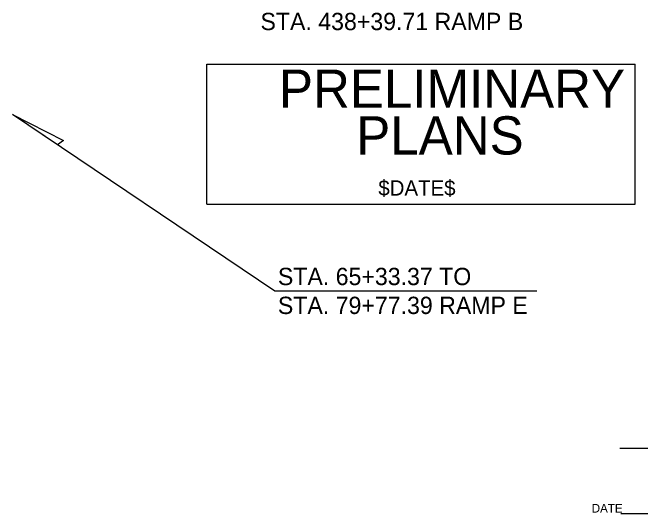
# Model space of a CAD drawing. Extents: x 2121385 to 2181200, y 132498 to 161273.
# Drawn here: x 2167716 to 2176434, y 136610 to 143556 of the extents above; entities that cross this region are included whole.
import ezdxf

# ---------------------------------------------------------------- set-up
doc = ezdxf.new("R2010")
doc.units = 0
for name, color, linetype in [('4', 7, 'Continuous'), ('5', 7, 'Continuous'), ('SHT_Date_Stamp', 7, 'Continuous'), ('SHT_Standard_Sheet_Lines', 7, 'Continuous'), ('SHT_Standard_Sheet_Txt', 7, 'Continuous'), ('TOPO_Concrete', 7, 'Continuous')]:
    doc.layers.add(name, color=color, linetype=linetype)

# ---------------------------------------------------------------- blocks, each defined once
blk = doc.blocks.new('Stamp_Date_Stamp')
at = {"layer": 'SHT_Date_Stamp'}
blk.add_text('$DATE$', height=0.12, dxfattribs=at).set_placement((-2.1838, -1.3809))

msp = doc.modelspace()

# ---------------------------------------------------------------- linework, layer by layer
at = {"layer": '5'}
msp.add_lwpolyline([(2167715.5, 142142.7), (2168423.1, 141780), (2168337.7, 141723.9)], close=True, dxfattribs=at)
msp.add_lwpolyline([(2174994.3, 139690.5), (2171359.3, 139690.5), (2167715.5, 142142.7)], dxfattribs=at)
at = {"layer": 'SHT_Standard_Sheet_Lines'}
for p, q in [((2176149.1, 137516), (2179078.2, 137516)), ((2176161.2, 136609.7), (2179090.3, 136609.7))]:
    msp.add_line(p, q, dxfattribs=at)
at = {"layer": 'TOPO_Concrete'}
for p, q in [((2170410.8, 142840), (2176359.2, 142840)), ((2170410.8, 140897.4), (2170410.8, 142840)), ((2176359.2, 140897.4), (2176359.2, 142840)), ((2170410.8, 140897.4), (2176359.2, 140897.4))]:
    msp.add_line(p, q, dxfattribs=at)

# ---------------------------------------------------------------- block references
at = {"layer": 'TOPO_Concrete', "xscale": 1767.295568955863, "yscale": 1767.295568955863}
msp.add_blockref('Stamp_Date_Stamp', (2176653.7, 143458.6), dxfattribs=at)

# ---------------------------------------------------------------- texts
at = {"layer": '4'}
for s, p in [('STA. 438+39.71 RAMP B', (2171157.9, 143312.7)), ('STA. 65+33.37 TO', (2171399.7, 139776.1)), ('STA. 79+77.39 RAMP E', (2171399.7, 139375.3))]:
    msp.add_text(s, height=240, dxfattribs=at).set_placement(p)
at = {"layer": 'SHT_Standard_Sheet_Txt'}
msp.add_text('DATE', height=120, dxfattribs=at).set_placement((2175757.6, 136621.4))
at = {"layer": 'TOPO_Concrete'}
for s, height, p in [('PRELIMINARY', 530.189, (2171414.5, 142235.6)), ('PLANS', 530.19, (2172487.4, 141587.6))]:
    msp.add_text(s, height=height, dxfattribs=at).set_placement(p)

doc.saveas('drawing.dxf')
